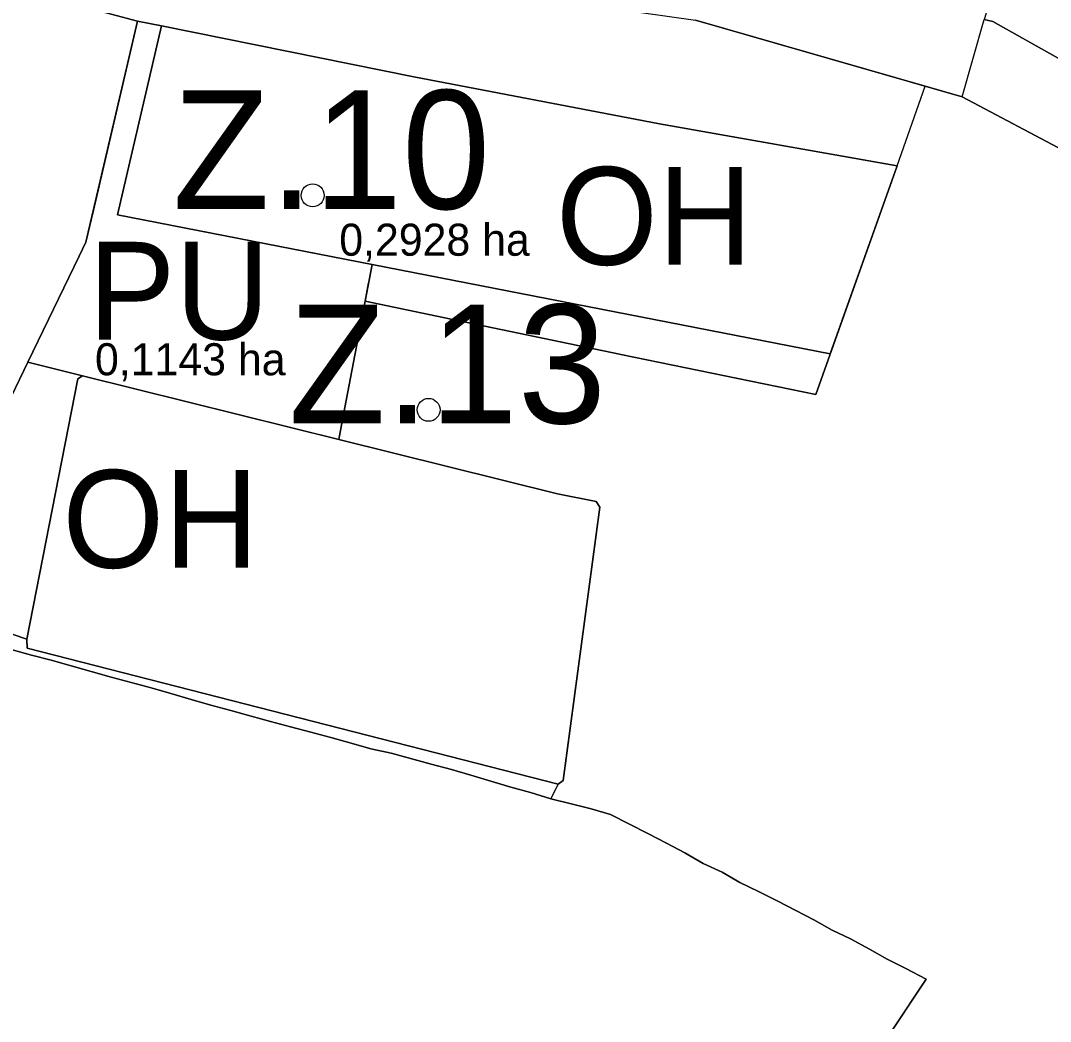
# Model space of a CAD drawing. Extents: x -555509 to -553005, y -1186756 to -1182560.
# Drawn here: x -554216.4 to -554068.9, y -1185446.2 to -1185302.9 of the extents above; entities that cross this region are included whole.
import ezdxf

# ---------------------------------------------------------------- set-up
doc = ezdxf.new("R2010")
doc.units = 0
for name, color, linetype in [('Level 15', 7, 'Continuous'), ('Level 26', 7, 'Continuous'), ('Level 29', 7, 'Continuous'), ('Level 36', 7, 'Continuous'), ('Level 4', 7, 'Continuous'), ('Level 46', 7, 'Continuous'), ('Level 47', 7, 'Continuous'), ('Level 49', 7, 'Continuous'), ('Level 52', 7, 'Continuous'), ('Level 56', 7, 'Continuous'), ('Level 59', 7, 'Continuous'), ('Level 6', 7, 'Continuous'), ('Level 63', 7, 'Continuous'), ('navrh_PU', 7, 'Continuous'), ('OBRYS_PLOCH', 7, 'Continuous'), ('stav_AL', 7, 'Continuous'), ('stav_DS', 7, 'Continuous'), ('stav_PU', 7, 'Continuous'), ('stav_ZK', 7, 'Continuous'), ('stav_ZZ', 7, 'Continuous')]:
    doc.layers.add(name, color=color, linetype=linetype)

msp = doc.modelspace()

# ---------------------------------------------------------------- linework, layer by layer
at = {"layer": 'Level 15'}
for p, q in [((-554215.46, -1185391.51), (-554227.43, -1185387.45)), ((-554227.43, -1185387.45), (-554215.46, -1185391.51))]:
    msp.add_line(p, q, dxfattribs=at)
for points in [[(-554215.31, -1185351.82), (-554219.51, -1185360.48)], [(-554207.47, -1185353.77), (-554215.31, -1185351.82)], [(-554215.46, -1185391.51), (-554208.17, -1185354.22), (-554207.47, -1185353.77)], [(-554139.35, -1185412.26), (-554215.41, -1185392.77), (-554215.46, -1185391.51)], [(-554217.7, -1185393), (-554214.79, -1185393.8), (-554211.96, -1185394.51), (-554206.24, -1185396.12), (-554203.39, -1185396.92), (-554200.52, -1185397.7), (-554197.65, -1185398.48)], [(-554197.65, -1185398.48), (-554194.84, -1185399.3), (-554191.94, -1185400.12), (-554189.13, -1185400.95), (-554186.22, -1185401.71), (-554183.34, -1185402.51), (-554180.56, -1185403.31), (-554177.68, -1185404.06), (-554174.8, -1185404.81), (-554171.92, -1185405.59), (-554169.02, -1185406.37), (-554166.17, -1185407.19), (-554163.28, -1185407.81), (-554157.54, -1185409.41), (-554154.64, -1185410.18), (-554151.85, -1185410.99), (-554148.99, -1185411.84), (-554146.12, -1185412.68), (-554143.3, -1185413.46), (-554140.43, -1185414.36)], [(-554140.43, -1185414.36), (-554139.35, -1185412.26)]]:
    msp.add_lwpolyline(points, dxfattribs=at)
at = {"layer": 'Level 26'}
msp.add_lwpolyline([(-554070.29, -1185277.21), (-554073.1, -1185286.11), (-554078.34, -1185302.74), (-554077.12, -1185303.07), (-554067.41, -1185308.49), (-554061.58, -1185289.53), (-554056.72, -1185273.74), (-554044.05, -1185254.33), (-554020.12, -1185246.87), (-554002.44, -1185238.44)], dxfattribs=at)
at = {"layer": 'Level 36'}
for p, q in [((-554090.82, -1185323.71), (-554086.79, -1185312.33)), ((-554100.38, -1185350.64), (-554090.82, -1185323.71)), ((-554166.01, -1185337.84), (-554166.01, -1185337.84)), ((-554166.01, -1185337.84), (-554100.38, -1185350.64))]:
    msp.add_line(p, q, dxfattribs=at)
for points in [[(-554086.79, -1185312.33), (-554081.51, -1185313.86), (-554066.15, -1185321.95), (-554045.89, -1185338.45), (-553973.36, -1185402.64), (-553974.35, -1185411.9), (-553991.45, -1185519.3), (-553963.43, -1185534.75), (-553931.3, -1185554.25), (-553895.22, -1185571.18), (-553862.7, -1185585.67), (-553858.01, -1185587.49), (-553842.47, -1185594.31), (-553824.8, -1185598.76)], [(-554170.79, -1185362.9), (-554170.79, -1185362.9), (-554166.01, -1185337.84)], [(-554197.65, -1185398.48), (-554194.84, -1185399.3), (-554191.94, -1185400.12), (-554189.13, -1185400.95), (-554186.22, -1185401.71), (-554183.34, -1185402.51), (-554180.56, -1185403.31), (-554177.68, -1185404.06), (-554174.8, -1185404.81), (-554171.92, -1185405.59), (-554169.02, -1185406.37), (-554166.17, -1185407.19), (-554163.28, -1185407.81), (-554157.54, -1185409.41), (-554154.64, -1185410.18), (-554151.85, -1185410.99), (-554148.99, -1185411.84), (-554146.12, -1185412.68), (-554143.3, -1185413.46), (-554140.43, -1185414.36), (-554139.35, -1185412.26), (-554138.66, -1185411.73), (-554133.37, -1185372.6), (-554133.9, -1185371.8), (-554139.47, -1185370.7), (-554170.79, -1185362.9)], [(-554228.22, -1185390.17), (-554226.4, -1185390.71), (-554223.52, -1185391.45), (-554220.62, -1185392.2), (-554217.7, -1185393), (-554214.79, -1185393.8), (-554211.96, -1185394.51), (-554206.24, -1185396.12), (-554203.39, -1185396.92), (-554200.52, -1185397.7), (-554197.65, -1185398.48)]]:
    msp.add_lwpolyline(points, dxfattribs=at)
at = {"layer": 'Level 4'}
for centre in [(-554174.52, -1185327.95), (-554157.92, -1185358.66)]:
    msp.add_circle(centre, 1.64, dxfattribs=at)
at = {"layer": 'Level 47'}
for p, q in [((-554196.15, -1185303.69), (-554202.48, -1185330.72)), ((-554160.01, -1185310.95), (-554196.15, -1185303.69)), ((-554124.84, -1185317.69), (-554160.01, -1185310.95)), ((-554090.82, -1185323.71), (-554124.84, -1185317.69)), ((-554100.38, -1185350.64), (-554090.82, -1185323.71)), ((-554202.48, -1185330.72), (-554100.38, -1185350.64))]:
    msp.add_line(p, q, dxfattribs=at)
at = {"layer": 'Level 49'}
for points in [[(-554207.47, -1185353.77), (-554208.17, -1185354.22), (-554215.46, -1185391.51), (-554215.41, -1185392.77), (-554139.35, -1185412.26), (-554139.35, -1185412.26)], [(-554138.66, -1185411.73), (-554133.37, -1185372.6), (-554133.9, -1185371.8), (-554139.47, -1185370.7), (-554207.47, -1185353.77)], [(-554139.35, -1185412.26), (-554138.66, -1185411.73)]]:
    msp.add_lwpolyline(points, dxfattribs=at)
at = {"layer": 'Level 52'}
for points in [[(-554119.67, -1185302.84), (-554081.51, -1185313.86), (-554078.34, -1185302.74)], [(-554307.28, -1185451.33), (-554306.61, -1185445.15), (-554298.85, -1185373.97), (-554298.18, -1185367.84), (-554317.24, -1185362.56), (-554317.5, -1185346.39), (-554317.99, -1185332.29), (-554257.37, -1185356.67), (-554223.04, -1185370.47), (-554225.01, -1185379.12), (-554227.43, -1185387.45), (-554228.22, -1185390.17), (-554226.4, -1185390.71), (-554223.52, -1185391.45), (-554220.62, -1185392.2), (-554217.7, -1185393), (-554214.79, -1185393.8), (-554211.96, -1185394.51), (-554206.24, -1185396.12), (-554203.39, -1185396.92), (-554200.52, -1185397.7), (-554197.65, -1185398.48)], [(-554197.65, -1185398.48), (-554194.84, -1185399.3), (-554191.94, -1185400.12), (-554189.13, -1185400.95), (-554186.22, -1185401.71), (-554183.34, -1185402.51), (-554180.56, -1185403.31), (-554177.68, -1185404.06), (-554174.8, -1185404.81), (-554171.92, -1185405.59), (-554169.02, -1185406.37), (-554166.17, -1185407.19), (-554163.28, -1185407.81), (-554157.54, -1185409.41), (-554154.64, -1185410.18), (-554151.85, -1185410.99), (-554148.99, -1185411.84), (-554146.12, -1185412.68), (-554143.3, -1185413.46), (-554140.43, -1185414.36), (-554139.35, -1185412.26), (-554138.66, -1185411.73), (-554133.37, -1185372.6), (-554133.9, -1185371.8), (-554139.47, -1185370.7), (-554207.47, -1185353.77), (-554215.31, -1185351.82), (-554219.51, -1185360.48)]]:
    msp.add_lwpolyline(points, dxfattribs=at)
at = {"layer": 'Level 56'}
for p, q in [((-554199.59, -1185303), (-554205.92, -1185330.05)), ((-554196.15, -1185303.69), (-554199.59, -1185303)), ((-554196.15, -1185303.69), (-554202.48, -1185330.72)), ((-554196.54, -1185305.34), (-554196.15, -1185303.69)), ((-554160.01, -1185310.95), (-554196.15, -1185303.69)), ((-554124.84, -1185317.69), (-554160.01, -1185310.95)), ((-554090.82, -1185323.71), (-554124.84, -1185317.69)), ((-554100.38, -1185350.64), (-554090.82, -1185323.71)), ((-554205.92, -1185330.05), (-554207, -1185334.66)), ((-554202.48, -1185330.72), (-554100.38, -1185350.64)), ((-554207, -1185334.66), (-554207.96, -1185336.64)), ((-554207.96, -1185336.64), (-554215.31, -1185351.82)), ((-554167.01, -1185343.09), (-554166.51, -1185340.46)), ((-554170.35, -1185360.59), (-554167.01, -1185343.09)), ((-554215.31, -1185351.82), (-554207.47, -1185353.77)), ((-554207.47, -1185353.77), (-554170.79, -1185362.9)), ((-554170.79, -1185362.9), (-554170.35, -1185360.59)), ((-554170.79, -1185362.9), (-554170.79, -1185362.9))]:
    msp.add_line(p, q, dxfattribs=at)
at = {"layer": 'Level 6'}
for points in [[(-554119.67, -1185302.84), (-554081.51, -1185313.86), (-554078.34, -1185302.74)], [(-554307.28, -1185451.33), (-554306.61, -1185445.15), (-554298.85, -1185373.97), (-554298.18, -1185367.84), (-554317.24, -1185362.56), (-554317.5, -1185346.39), (-554317.99, -1185332.29), (-554257.37, -1185356.67), (-554223.04, -1185370.47), (-554225.01, -1185379.12), (-554227.43, -1185387.45), (-554228.22, -1185390.17), (-554226.4, -1185390.71), (-554223.52, -1185391.45), (-554220.62, -1185392.2), (-554217.7, -1185393), (-554214.79, -1185393.8), (-554211.96, -1185394.51), (-554206.24, -1185396.12), (-554203.39, -1185396.92), (-554200.52, -1185397.7), (-554197.65, -1185398.48)], [(-554197.65, -1185398.48), (-554194.84, -1185399.3), (-554191.94, -1185400.12), (-554189.13, -1185400.95), (-554186.22, -1185401.71), (-554183.34, -1185402.51), (-554180.56, -1185403.31), (-554177.68, -1185404.06), (-554174.8, -1185404.81), (-554171.92, -1185405.59), (-554169.02, -1185406.37), (-554166.17, -1185407.19), (-554163.28, -1185407.81), (-554157.54, -1185409.41), (-554154.64, -1185410.18), (-554151.85, -1185410.99), (-554148.99, -1185411.84), (-554146.12, -1185412.68), (-554143.3, -1185413.46), (-554140.43, -1185414.36), (-554139.35, -1185412.26), (-554138.66, -1185411.73), (-554133.37, -1185372.6), (-554133.9, -1185371.8), (-554139.47, -1185370.7), (-554207.47, -1185353.77), (-554215.31, -1185351.82), (-554219.51, -1185360.48)]]:
    msp.add_lwpolyline(points, dxfattribs=at)
at = {"layer": 'navrh_PU'}
for p, q in [((-554196.15, -1185303.69), (-554199.59, -1185303)), ((-554202.48, -1185330.72), (-554196.15, -1185303.69)), ((-554166.01, -1185337.84), (-554202.48, -1185330.72)), ((-554207, -1185334.66), (-554207.96, -1185336.64)), ((-554207.96, -1185336.64), (-554215.31, -1185351.82)), ((-554167.01, -1185343.09), (-554166.01, -1185337.84)), ((-554215.31, -1185351.82), (-554207.47, -1185353.77)), ((-554207.47, -1185353.77), (-554170.79, -1185362.9)), ((-554170.79, -1185362.9), (-554170.79, -1185362.9))]:
    msp.add_line(p, q, dxfattribs=at)
for points in [[(-554199.59, -1185303), (-554205.92, -1185330.05), (-554207, -1185334.66)], [(-554170.79, -1185362.9), (-554170.35, -1185360.59), (-554167.01, -1185343.09)]]:
    msp.add_lwpolyline(points, dxfattribs=at)
at = {"layer": 'OBRYS_PLOCH'}
for p, q in [((-554199.59, -1185303), (-554237.4, -1185292.88)), ((-554237.4, -1185292.88), (-554199.59, -1185303)), ((-554207, -1185334.66), (-554199.59, -1185303)), ((-554199.59, -1185303), (-554196.15, -1185303.69)), ((-554196.15, -1185303.69), (-554199.59, -1185303)), ((-554119.67, -1185302.84), (-554086.79, -1185312.33)), ((-554086.79, -1185312.33), (-554119.67, -1185302.84)), ((-554202.48, -1185330.72), (-554196.15, -1185303.69)), ((-554196.15, -1185303.69), (-554202.48, -1185330.72)), ((-554196.15, -1185303.69), (-554160.01, -1185310.95)), ((-554160.01, -1185310.95), (-554196.15, -1185303.69)), ((-554160.01, -1185310.95), (-554124.84, -1185317.69)), ((-554124.84, -1185317.69), (-554160.01, -1185310.95)), ((-554086.79, -1185312.33), (-554081.51, -1185313.86)), ((-554081.51, -1185313.86), (-554066.15, -1185321.95)), ((-554124.84, -1185317.69), (-554090.82, -1185323.71)), ((-554090.82, -1185323.71), (-554124.84, -1185317.69)), ((-554090.82, -1185323.71), (-554102.45, -1185356.48)), ((-554100.38, -1185350.64), (-554090.82, -1185323.71)), ((-554166.01, -1185337.84), (-554202.48, -1185330.72)), ((-554202.48, -1185330.72), (-554100.38, -1185350.64)), ((-554207.96, -1185336.64), (-554207, -1185334.66)), ((-554207, -1185334.66), (-554207.96, -1185336.64)), ((-554215.31, -1185351.82), (-554207.96, -1185336.64)), ((-554207.96, -1185336.64), (-554215.31, -1185351.82)), ((-554167.01, -1185343.09), (-554166.01, -1185337.84)), ((-554167.01, -1185343.09), (-554170.35, -1185360.59)), ((-554154.69, -1185345.69), (-554167.01, -1185343.09)), ((-554130.56, -1185350.67), (-554154.69, -1185345.69)), ((-554219.51, -1185360.48), (-554215.31, -1185351.82)), ((-554215.31, -1185351.82), (-554207.47, -1185353.77)), ((-554130.38, -1185350.71), (-554130.56, -1185350.67)), ((-554102.45, -1185356.48), (-554130.38, -1185350.71)), ((-554207.47, -1185353.77), (-554170.79, -1185362.9)), ((-554170.35, -1185360.59), (-554170.79, -1185362.9)), ((-554170.79, -1185362.9), (-554170.79, -1185362.9)), ((-554170.79, -1185362.9), (-554170.79, -1185362.9)), ((-554133.37, -1185372.6), (-554138.66, -1185411.73)), ((-554133.9, -1185371.8), (-554133.37, -1185372.6)), ((-554139.35, -1185412.26), (-554140.43, -1185414.36)), ((-554138.66, -1185411.73), (-554139.35, -1185412.26)), ((-554140.43, -1185414.36), (-554137.51, -1185415.07)), ((-554137.51, -1185415.07), (-554134.63, -1185415.78)), ((-554134.63, -1185415.78), (-554131.86, -1185416.61)), ((-554131.86, -1185416.61), (-554129.16, -1185417.97)), ((-554123.86, -1185420.72), (-554121.2, -1185422.09)), ((-554121.2, -1185422.09), (-554118.58, -1185423.63)), ((-554118.58, -1185423.63), (-554115.87, -1185424.86)), ((-554110.66, -1185427.61), (-554108, -1185428.97)), ((-554108, -1185428.97), (-554105.33, -1185430.33)), ((-554105.33, -1185430.33), (-554102.72, -1185431.7)), ((-554102.72, -1185431.7), (-554100.13, -1185433.15)), ((-554100.13, -1185433.15), (-554097.46, -1185434.4)), ((-554097.46, -1185434.4), (-554094.78, -1185435.91)), ((-554094.78, -1185435.91), (-554092.21, -1185437.3)), ((-554092.21, -1185437.3), (-554089.57, -1185438.64)), ((-554089.57, -1185438.64), (-554086.65, -1185440.17)), ((-554086.65, -1185440.17), (-554095.82, -1185454))]:
    msp.add_line(p, q, dxfattribs=at)
for points in [[(-554070.29, -1185277.21), (-554073.1, -1185286.11), (-554078.34, -1185302.74), (-554077.12, -1185303.07), (-554067.41, -1185308.49), (-554061.58, -1185289.53), (-554056.72, -1185273.74), (-554044.05, -1185254.33), (-554020.12, -1185246.87), (-554002.44, -1185238.44)], [(-554199.59, -1185303), (-554205.92, -1185330.05), (-554207, -1185334.66)], [(-554199.59, -1185303), (-554205.92, -1185330.05), (-554207, -1185334.66)], [(-554067.41, -1185308.49), (-554077.12, -1185303.07), (-554078.34, -1185302.74)], [(-554066.15, -1185321.95), (-554081.51, -1185313.86), (-554086.79, -1185312.33)], [(-554170.79, -1185362.9), (-554170.35, -1185360.59), (-554167.01, -1185343.09)], [(-554207.47, -1185353.77), (-554208.17, -1185354.22), (-554215.46, -1185391.51), (-554215.41, -1185392.77), (-554139.35, -1185412.26), (-554139.35, -1185412.26)], [(-554138.66, -1185411.73), (-554133.37, -1185372.6), (-554133.9, -1185371.8), (-554139.47, -1185370.7), (-554207.47, -1185353.77)], [(-554170.79, -1185362.9), (-554139.47, -1185370.7), (-554133.9, -1185371.8)], [(-554197.65, -1185398.48), (-554200.52, -1185397.7), (-554203.39, -1185396.92), (-554206.24, -1185396.12), (-554211.96, -1185394.51), (-554214.79, -1185393.8), (-554217.7, -1185393)], [(-554140.43, -1185414.36), (-554143.3, -1185413.46), (-554146.12, -1185412.68), (-554148.99, -1185411.84), (-554151.85, -1185410.99), (-554154.64, -1185410.18), (-554157.54, -1185409.41), (-554163.28, -1185407.81), (-554166.17, -1185407.19), (-554169.02, -1185406.37), (-554171.92, -1185405.59), (-554174.8, -1185404.81), (-554177.68, -1185404.06), (-554180.56, -1185403.31), (-554183.34, -1185402.51), (-554186.22, -1185401.71), (-554189.13, -1185400.95), (-554191.94, -1185400.12), (-554194.84, -1185399.3), (-554197.65, -1185398.48)], [(-554139.35, -1185412.26), (-554138.66, -1185411.73)], [(-554095.82, -1185454), (-554086.65, -1185440.17), (-554089.57, -1185438.64), (-554092.21, -1185437.3), (-554094.78, -1185435.91), (-554097.46, -1185434.4), (-554100.13, -1185433.15), (-554102.72, -1185431.7), (-554105.33, -1185430.33), (-554108, -1185428.97), (-554110.66, -1185427.61), (-554113.33, -1185426.32), (-554115.87, -1185424.86), (-554118.58, -1185423.63), (-554121.2, -1185422.09), (-554123.86, -1185420.72), (-554126.51, -1185419.33), (-554129.16, -1185417.97), (-554131.86, -1185416.61), (-554134.63, -1185415.78), (-554137.51, -1185415.07), (-554140.43, -1185414.36)], [(-554129.16, -1185417.97), (-554126.51, -1185419.33), (-554123.86, -1185420.72)], [(-554115.87, -1185424.86), (-554113.33, -1185426.32), (-554110.66, -1185427.61)]]:
    msp.add_lwpolyline(points, dxfattribs=at)
at = {"layer": 'stav_AL'}
for p, q in [((-554102.45, -1185356.48), (-554090.82, -1185323.71)), ((-554090.82, -1185323.71), (-554100.38, -1185350.64)), ((-554100.38, -1185350.64), (-554202.48, -1185330.72)), ((-554202.48, -1185330.72), (-554166.01, -1185337.84)), ((-554166.01, -1185337.84), (-554167.01, -1185343.09)), ((-554130.56, -1185350.67), (-554130.38, -1185350.71)), ((-554130.38, -1185350.71), (-554102.45, -1185356.48))]:
    msp.add_line(p, q, dxfattribs=at)
msp.add_lwpolyline([(-554167.01, -1185343.09), (-554154.69, -1185345.69), (-554130.56, -1185350.67)], dxfattribs=at)
at = {"layer": 'stav_DS'}
for points in [[(-554179.88, -1185294.33), (-554119.67, -1185302.84), (-554086.79, -1185312.33), (-554081.51, -1185313.86), (-554066.15, -1185321.95), (-554045.89, -1185338.45)], [(-554067.41, -1185308.49), (-554077.12, -1185303.07), (-554078.34, -1185302.74)]]:
    msp.add_lwpolyline(points, dxfattribs=at)
at = {"layer": 'stav_PU'}
for p, q in [((-554215.31, -1185351.82), (-554219.51, -1185360.48)), ((-554207.47, -1185353.77), (-554215.31, -1185351.82)), ((-554140.43, -1185414.36), (-554139.35, -1185412.26))]:
    msp.add_line(p, q, dxfattribs=at)
for points in [[(-554215.46, -1185391.51), (-554208.17, -1185354.22), (-554207.47, -1185353.77)], [(-554139.35, -1185412.26), (-554215.41, -1185392.77), (-554215.46, -1185391.51)], [(-554217.7, -1185393), (-554214.79, -1185393.8), (-554211.96, -1185394.51), (-554206.24, -1185396.12), (-554203.39, -1185396.92), (-554200.52, -1185397.7), (-554197.65, -1185398.48)], [(-554197.65, -1185398.48), (-554194.84, -1185399.3), (-554191.94, -1185400.12), (-554189.13, -1185400.95), (-554186.22, -1185401.71), (-554183.34, -1185402.51), (-554180.56, -1185403.31), (-554177.68, -1185404.06), (-554174.8, -1185404.81), (-554171.92, -1185405.59), (-554169.02, -1185406.37), (-554166.17, -1185407.19), (-554163.28, -1185407.81), (-554157.54, -1185409.41), (-554154.64, -1185410.18), (-554151.85, -1185410.99), (-554148.99, -1185411.84), (-554146.12, -1185412.68), (-554143.3, -1185413.46), (-554140.43, -1185414.36)]]:
    msp.add_lwpolyline(points, dxfattribs=at)
at = {"layer": 'stav_ZK'}
for p, q in [((-554237.4, -1185292.88), (-554199.59, -1185303)), ((-554199.59, -1185303), (-554196.15, -1185303.69)), ((-554086.79, -1185312.33), (-554119.67, -1185302.84)), ((-554196.15, -1185303.69), (-554160.01, -1185310.95)), ((-554160.01, -1185310.95), (-554124.84, -1185317.69)), ((-554081.51, -1185313.86), (-554086.79, -1185312.33)), ((-554066.15, -1185321.95), (-554081.51, -1185313.86)), ((-554124.84, -1185317.69), (-554090.82, -1185323.71)), ((-554090.82, -1185323.71), (-554102.45, -1185356.48)), ((-554130.38, -1185350.71), (-554130.56, -1185350.67)), ((-554102.45, -1185356.48), (-554130.38, -1185350.71)), ((-554170.79, -1185362.9), (-554170.79, -1185362.9)), ((-554139.35, -1185412.26), (-554140.43, -1185414.36)), ((-554138.66, -1185411.73), (-554139.35, -1185412.26)), ((-554140.43, -1185414.36), (-554137.51, -1185415.07)), ((-554137.51, -1185415.07), (-554134.63, -1185415.78)), ((-554134.63, -1185415.78), (-554131.86, -1185416.61)), ((-554126.51, -1185419.33), (-554123.86, -1185420.72)), ((-554123.86, -1185420.72), (-554121.2, -1185422.09)), ((-554121.2, -1185422.09), (-554118.58, -1185423.63)), ((-554086.65, -1185440.17), (-554095.82, -1185454))]:
    msp.add_line(p, q, dxfattribs=at)
for points in [[(-554167.01, -1185343.09), (-554170.35, -1185360.59), (-554170.79, -1185362.9)], [(-554130.56, -1185350.67), (-554154.69, -1185345.69), (-554167.01, -1185343.09)], [(-554170.79, -1185362.9), (-554139.47, -1185370.7), (-554133.9, -1185371.8), (-554133.37, -1185372.6), (-554138.66, -1185411.73)], [(-554131.86, -1185416.61), (-554129.16, -1185417.97), (-554126.51, -1185419.33)], [(-554118.58, -1185423.63), (-554115.87, -1185424.86), (-554113.33, -1185426.32)], [(-554113.33, -1185426.32), (-554110.66, -1185427.61), (-554108, -1185428.97)], [(-554108, -1185428.97), (-554105.33, -1185430.33), (-554102.72, -1185431.7)], [(-554102.72, -1185431.7), (-554100.13, -1185433.15), (-554097.46, -1185434.4)], [(-554097.46, -1185434.4), (-554094.78, -1185435.91), (-554092.21, -1185437.3), (-554089.57, -1185438.64), (-554086.65, -1185440.17)]]:
    msp.add_lwpolyline(points, dxfattribs=at)
at = {"layer": 'stav_ZZ'}
for p, q in [((-554199.59, -1185303), (-554237.4, -1185292.88)), ((-554207, -1185334.66), (-554199.59, -1185303)), ((-554219.51, -1185360.48), (-554215.31, -1185351.82))]:
    msp.add_line(p, q, dxfattribs=at)
for points in [[(-554215.31, -1185351.82), (-554207.96, -1185336.64), (-554207, -1185334.66)], [(-554197.65, -1185398.48), (-554200.52, -1185397.7), (-554203.39, -1185396.92), (-554206.24, -1185396.12), (-554211.96, -1185394.51), (-554214.79, -1185393.8), (-554217.7, -1185393)], [(-554140.43, -1185414.36), (-554143.3, -1185413.46), (-554146.12, -1185412.68), (-554148.99, -1185411.84), (-554151.85, -1185410.99), (-554154.64, -1185410.18), (-554157.54, -1185409.41), (-554163.28, -1185407.81), (-554166.17, -1185407.19), (-554169.02, -1185406.37), (-554171.92, -1185405.59), (-554174.8, -1185404.81), (-554177.68, -1185404.06), (-554180.56, -1185403.31), (-554183.34, -1185402.51), (-554186.22, -1185401.71), (-554189.13, -1185400.95), (-554191.94, -1185400.12), (-554194.84, -1185399.3), (-554197.65, -1185398.48)], [(-554095.82, -1185454), (-554086.65, -1185440.17), (-554089.57, -1185438.64), (-554092.21, -1185437.3), (-554094.78, -1185435.91), (-554097.46, -1185434.4), (-554100.13, -1185433.15), (-554102.72, -1185431.7), (-554105.33, -1185430.33), (-554108, -1185428.97), (-554110.66, -1185427.61), (-554113.33, -1185426.32), (-554115.87, -1185424.86), (-554118.58, -1185423.63), (-554121.2, -1185422.09), (-554123.86, -1185420.72), (-554126.51, -1185419.33), (-554129.16, -1185417.97), (-554131.86, -1185416.61), (-554134.63, -1185415.78), (-554137.51, -1185415.07), (-554140.43, -1185414.36)]]:
    msp.add_lwpolyline(points, dxfattribs=at)

# ---------------------------------------------------------------- texts
at = {"layer": 'Level 29'}
for s, p in [('0,2928 ha', (-554170.71, -1185336.59)), ('0,1143 ha', (-554205.7, -1185353.71))]:
    msp.add_text(s, height=4.588, dxfattribs=at).set_placement(p)
at = {"layer": 'Level 46'}
for s, p in [('Z.10', (-554194.57, -1185329.89)), ('Z.13', (-554177.97, -1185360.59))]:
    msp.add_text(s, height=17, dxfattribs=at).set_placement(p)
at = {"layer": 'Level 59'}
msp.add_text('OH', height=14, dxfattribs=at).set_placement((-554210.36, -1185381.28))
at = {"layer": 'Level 63'}
for s, p in [('OH', (-554139.65, -1185337.89)), ('PU', (-554206.68, -1185348.6))]:
    msp.add_text(s, height=14, dxfattribs=at).set_placement(p)

doc.saveas('drawing.dxf')
